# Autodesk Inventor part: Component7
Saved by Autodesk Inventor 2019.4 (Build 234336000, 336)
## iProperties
Created: 2020-04
Part Number: Component7
Material: Generic
Document SubType Name: Modeling
Designer: Administrator
Density: 1 g/cm^3
Appearance: Default
Title: Component7
Author: Administrator
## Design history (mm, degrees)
feature "Body1"
body "Solid1"
